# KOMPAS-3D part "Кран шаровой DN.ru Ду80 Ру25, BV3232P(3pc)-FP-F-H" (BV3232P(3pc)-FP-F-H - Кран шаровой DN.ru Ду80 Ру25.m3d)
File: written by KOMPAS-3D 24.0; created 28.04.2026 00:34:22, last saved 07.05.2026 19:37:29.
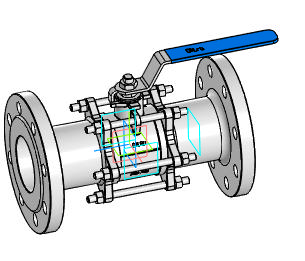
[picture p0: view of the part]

Document properties: Автор: Максим; Полное имя файла: BVxxP(3pc)-FP-F-H - Кран шаровой DN.ru Ду80 Ру25.cdw

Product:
- Body: Тело 1  | qty 1
    Масса: 14.35719
- Part/product: Кран шаровой DN.ru Ду80 Ру25  | designation BV3232P(3pc)-FP-F-H
    Масса: 16.665
    Раздел спецификации: Прочие изделия
    Форматы листов документа: A3
    Примечание: D160-22808

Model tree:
1. Операция без истории:1
2. Эскиз:1  (with: Ребро.Операция без истории:1)
3. Элемент выдавливания:1
     Расстояние 1 = 11
4. Скругление:1  (with: Ребро.Элемент выдавливания:1)
     Радиус = 4
5. Скругление:2  (with: Ребро.Элемент выдавливания:1)
     Радиус = 8
6. Эскиз:3  (with: Ребро.Элемент выдавливания:1)
7. Элемент выдавливания:2
     Расстояние 1 = 31
8. Фаска:1  (with: Ребро.Элемент выдавливания:2)
     Угол = 45; Длина 1 = 8; Длина 2 = 8
9. Скругление:3  (with: Ребро.Элемент выдавливания:1)
     Радиус = 4
10. Скругление:4  (with: Ребро.Элемент выдавливания:1)
     Радиус = 8
11. Эскиз:4  (with: Ребро.Элемент выдавливания:2)
12. Элемент выдавливания:3
     Расстояние 1 = 32
13. Скругление:5  (with: Ребро.Элемент выдавливания:3)
     Радиус = 10
14. Скругление:6  (with: Ребро.Элемент выдавливания:3)
     Радиус = 0.5
15. Эскиз:5  (with: Грань.Операция без истории:1, Ребро.Операция без истории:1)
16. Элемент выдавливания:4  (with: Грань.Операция без истории:1)
     Расстояние 2 = 310
17. Смещенная плоскость:1
     Расстояние = -95
18. Эскиз:6  (with: Ребро.Операция без истории:1)
19. Элемент выдавливания:5
     Расстояние 1 = 39
20. Зеркальный массив:1
21. Экземпляр ( 1 )
22. Экземпляр ( 2 )  (with: Элемент выдавливания:5)
23. Смещенная плоскость:2
     Расстояние = 49
24. Эскиз:7
25. Элемент выдавливания:6  (with: Грань.Операция без истории:1)
     Расстояние 1 = -4.78298
26. Эскиз:8
27. Элемент выдавливания:7
     Расстояние 1 = 44
28. Эскиз:10  (with: Грань.Операция без истории:1)
29. Элемент выдавливания:8
     Расстояние 1 = 10
30. Зеркальный массив:2  (with: Экземпляр ( 1 ), Экземпляр ( 2 ), Элемент выдавливания:8)
31. Эскиз:12  (with: Грань.Элемент выдавливания:8, Ребро.Операция без истории:1)
32. Элемент вращения:1
     Угол 1 = 360
33. Зеркальный массив:3  (with: Экземпляр ( 1 ), Экземпляр ( 2 ), Элемент вращения:1)
34. Смещенная плоскость:3
     Расстояние = 49
35. Эскиз:13
36. Элемент выдавливания:9  (with: Грань.Операция без истории:1)
     Расстояние 1 = -5.40968
37. Зеркальный массив:4  (with: Экземпляр ( 1 ), Экземпляр ( 2 ), Элемент выдавливания:7)
38. Эскиз:14  (with: Грань.Элемент выдавливания:3, Ребро.Скругление:6, Ребро.Элемент выдавливания:3)
39. Элемент выдавливания:10
     Расстояние 2 = 0.2
40. Эскиз:15  (with: Грань.Операция без истории:1)
41. Элемент выдавливания:11
     Расстояние 2 = 30
42. Элемент выдавливания:12  (with: Грань.Элемент выдавливания:11)
     Расстояние 1 = 30

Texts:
  BV3232P(3pc)-FP-F-H
  DN80 PN25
